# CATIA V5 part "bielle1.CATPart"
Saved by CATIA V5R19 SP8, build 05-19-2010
Part number: bielle1
Bounding box of the stored display mesh (mm): x 0 to 50, y -119.864 to 119.864, z -1727.309 to 1226.253
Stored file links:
  C:\Users\ThinkMotion\Desktop\EU_thinkMotion\iao\IAO_MMS_Groupe3\gdespas\projet_Thinkmotion_GDESPAS\projet Thinkmotion GDESPAS\Assemblage gdespas\bielle1.CATPart
  C:\Users\ThinkMotion\Desktop\EU_thinkMotion\iao\IAO_MMS_Groupe3\gdespas\projet_Thinkmotion_GDESPAS\projet Thinkmotion GDESPAS\Assemblage gdespas\Bielle2.CATPart
  C:\Users\ThinkMotion\Desktop\EU_thinkMotion\iao\IAO_MMS_Groupe3\gdespas\projet_Thinkmotion_GDESPAS\projet Thinkmotion GDESPAS\Assemblage gdespas\Assemblage IAO.CATProduct
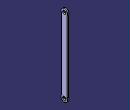
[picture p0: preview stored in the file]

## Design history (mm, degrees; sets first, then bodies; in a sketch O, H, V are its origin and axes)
External parameters (linked from other documents)
  External.diam_axe = 0.126
  External.entraxe_b1 = 2.71394
Body1 (main body)
  Sketch1 on yz-plane, origin (0, 0, 0), H (0, 1, 0), V (0, 0, 1)
    construction line L1 through (0, -897.5) direction (0, 1)
    point P1 (0, -1607.5)
    arc A1 centre (0, -1607.5) radius 120 from (-97, -1536.853) to (97, -1536.853) ccw
    point P2 (0, 1106.4441)
    arc A2 centre (0, 1106.4441) radius 120 from (97, 1035.7971) to (-97, 1035.7971) ccw
    line L2 (-97, 1035.7971) -> (-97, -1536.853)
    line L3 (97, 1035.7971) -> (97, -1536.853)
    point P3 (0, 1043.4441)
    circle A3 centre (0, 1106.4441) radius 63
    circle A4 centre (0, -1607.5) radius 63
    point P4 (0, 0)
    construction line L4 through (0, 0) direction (1, 0)
    reference intersected line E1 through (0, 0) direction (-1, 0) from xy-plane
    reference intersected line E2 through (0, 0) direction (0, 1) from zx-plane
    radius A1 = 120
    radius A2 = 120
    distance P2 P1 = 2713.9441 {= External.entraxe_b1}
    distance L3 L2 = 194
    distance L2 L1 = 97
    distance P1 = 710
    radius A4 = 63 {= External.diam_axe /2}
    radius A3 = 63 {= External.diam_axe /2}
    distance P1 E1 = 1607.5
    distance L2 E2 = 97
    coincidence: P1 L1, P2 L1, A3 P3, P3 L1
    vertical: L2 L1, L3 L1
  Pad1: profile Sketch1, direction (1, 0, 0), length 50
